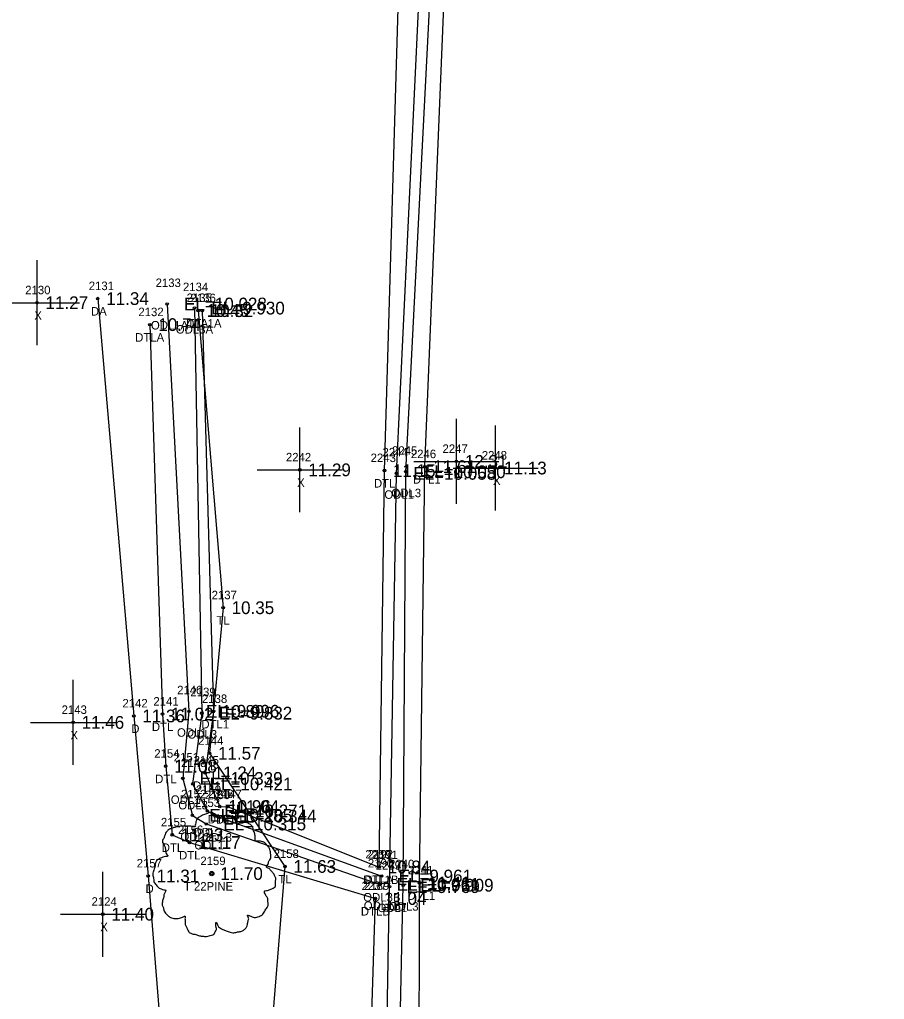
# Model space of a CAD drawing. Extents: x 2042211 to 2045853, y 303080 to 309569.
# Drawn here: x 2044366.6 to 2044468.4, y 304915.7 to 305031.1 of the extents above; entities that cross this region are included whole.
import ezdxf

# ---------------------------------------------------------------- set-up
doc = ezdxf.new("R2010")
doc.units = 0
for name, color, linetype in [('BR_500YR_SCOUR', 7, 'Continuous'), ('RD_EX_Driveway', 7, 'Continuous'), ('RD_EX_Driveway_txCode', 7, 'Continuous'), ('RD_EX_H2O', 7, 'Continuous'), ('RD_EX_H2O_txCode', 7, 'Continuous'), ('RD_EX_Misc', 7, 'Continuous'), ('RD_EX_Misc_txCode', 7, 'Continuous'), ('RD_EX_TX_Driveway_ELEV', 7, 'Continuous'), ('RD_EX_TX_H2O_ELEV', 7, 'Continuous'), ('RD_EX_TX_Misc_ELEV', 7, 'Continuous'), ('RD_EX_TX_VEG_ELEV', 7, 'Continuous'), ('RD_EX_VEG_txCode', 7, 'Continuous'), ('RD_SMD_Locator', 7, 'Continuous')]:
    doc.layers.add(name, color=color, linetype=linetype)

msp = doc.modelspace()

# ---------------------------------------------------------------- linework, layer by layer
at = {"layer": 'BR_500YR_SCOUR'}
msp.add_lwpolyline([(2044387.58, 304996.88), (2044390.53, 304961.86), (2044388.93, 304944.71), (2044397.82, 304931.38), (2044395.87, 304907.56), (2044407.42, 304883.17), (2044412.64, 304877.39), (2044413.34, 304846.91), (2044417.62, 304826.21), (2044417.53, 304827.99), (2044425.41, 304820.87), (2044430.68, 304811.06), (2044486.4, 304757.95), (2044546.53, 304677.07), (2044611.02, 304596.16), (2044662.5, 304521.9), (2044713.91, 304454.08), (2044725.96, 304441.86), (2044733.75, 304433.55)], dxfattribs=at)
for centre, radius in [((2044387.58, 304996.88), 0.15), ((2044390.53, 304961.86), 0.15), ((2044389.38, 304949.64), 0.15), ((2044388.93, 304944.71), 0.15), ((2044397.82, 304931.38), 0.15), ((2044389.19, 304930.54), 0.25), ((2044389.19, 304930.54), 0.15), ((2044389.18, 304930.52), 0.0001)]:
    msp.add_circle(centre, radius, dxfattribs=at)
for points in [[(2044389.32, 304937.71), (2044389.02, 304937.73), (2044388.7, 304937.63), (2044388.45, 304937.53), (2044388.23, 304937.46), (2044388, 304937.36), (2044387.7, 304937.18), (2044387.48, 304936.98), (2044387.35, 304936.73), (2044387.3, 304936.51), (2044387.25, 304936.23), (2044387.25, 304936.06), (2044387.13, 304936.03), (2044386.98, 304936.06), (2044386.73, 304936.13), (2044386.48, 304936.13), (2044386.23, 304936.13), (2044385.88, 304936.11), (2044385.53, 304936.11), (2044385.25, 304936.06), (2044384.93, 304936.01), (2044384.55, 304935.88), (2044384.2, 304935.76), (2044383.9, 304935.51), (2044383.65, 304935.03), (2044383.53, 304934.68), (2044383.38, 304934.44), (2044383.53, 304933.99), (2044383.7, 304933.64), (2044383.73, 304933.44), (2044383.8, 304933.01), (2044383.9, 304932.79), (2044384.03, 304932.59), (2044383.95, 304932.56), (2044383.58, 304932.51), (2044383.28, 304932.41), (2044382.85, 304932.19), (2044382.63, 304931.96), (2044382.53, 304931.64), (2044382.5, 304931.29), (2044382.4, 304931.09), (2044382.33, 304930.81), (2044382.3, 304930.74), (2044382.25, 304930.41), (2044382.35, 304929.96), (2044382.38, 304929.61), (2044382.5, 304929.39), (2044382.65, 304929.21), (2044382.83, 304928.96), (2044383.23, 304928.74), (2044383.55, 304928.64), (2044383.75, 304928.61), (2044383.58, 304928.11), (2044383.53, 304927.76), (2044383.4, 304927.36), (2044383.4, 304927.29), (2044383.35, 304926.81), (2044383.5, 304926.49), (2044383.58, 304926.11), (2044383.75, 304925.89), (2044384.03, 304925.59), (2044384.35, 304925.36), (2044384.85, 304925.24), (2044385.25, 304925.26), (2044385.83, 304925.44), (2044386.08, 304925.51), (2044386.05, 304925.34), (2044386.08, 304924.96), (2044386.08, 304924.54), (2044386.23, 304924.21), (2044386.33, 304923.94), (2044386.48, 304923.69), (2044386.8, 304923.46), (2044387.2, 304923.39), (2044387.63, 304923.24), (2044388.08, 304923.16), (2044388.58, 304923.14), (2044389.17, 304923.29), (2044389.45, 304923.41), (2044389.55, 304923.59), (2044389.75, 304923.96), (2044389.7, 304924.19), (2044389.72, 304924.79), (2044389.82, 304924.61), (2044390, 304924.26), (2044390.5, 304923.96), (2044390.9, 304923.79), (2044391.37, 304923.64), (2044391.67, 304923.56), (2044392.15, 304923.64), (2044392.52, 304923.71), (2044392.9, 304923.84), (2044393.2, 304924.11), (2044393.37, 304924.39), (2044393.42, 304924.66), (2044393.5, 304925.04), (2044393.55, 304925.21)], [(2044393.55, 304925.21), (2044393.47, 304925.39), (2044393.42, 304925.64), (2044393.5, 304925.61), (2044393.67, 304925.56), (2044393.95, 304925.44), (2044394.17, 304925.36), (2044394.5, 304925.39), (2044394.77, 304925.49), (2044395.22, 304925.76), (2044395.5, 304926.24), (2044395.77, 304926.64), (2044395.85, 304926.96), (2044395.8, 304927.19), (2044395.77, 304927.69), (2044395.57, 304927.94), (2044395.52, 304928.06), (2044395.42, 304928.46), (2044395.5, 304928.51), (2044395.77, 304928.56), (2044396.15, 304928.69), (2044396.42, 304928.81), (2044396.65, 304928.99), (2044396.72, 304929.21), (2044396.7, 304929.61), (2044396.75, 304930.01), (2044396.67, 304930.16), (2044396.57, 304930.31), (2044396.5, 304930.51), (2044396.35, 304930.66), (2044396.25, 304930.81), (2044396.15, 304930.91), (2044396.02, 304931.06), (2044395.85, 304931.19), (2044395.7, 304931.24), (2044395.65, 304931.39), (2044395.8, 304931.59), (2044395.85, 304931.69), (2044395.87, 304931.91), (2044396.1, 304932.26), (2044396.15, 304932.66), (2044396.1, 304933.09), (2044396.05, 304933.36), (2044395.9, 304933.64), (2044395.7, 304933.89), (2044395.57, 304934.06), (2044395.4, 304934.19), (2044395.07, 304934.31), (2044394.82, 304934.36), (2044394.47, 304934.36), (2044394.27, 304934.41), (2044394.3, 304934.46), (2044394.3, 304934.61), (2044394.3, 304934.88), (2044394.22, 304935.33), (2044394.07, 304935.83), (2044394.07, 304935.86), (2044393.97, 304936.11), (2044393.75, 304936.31), (2044393.57, 304936.41), (2044393.37, 304936.53), (2044393.12, 304936.56), (2044392.82, 304936.56), (2044392.55, 304936.51), (2044392.35, 304936.41), (2044392.17, 304936.28), (2044392.1, 304936.43), (2044392, 304936.73), (2044391.95, 304936.88), (2044391.8, 304937.06), (2044391.57, 304937.26), (2044391.12, 304937.38), (2044390.5, 304937.31), (2044390.2, 304937.11), (2044390.05, 304936.93), (2044390, 304937.06), (2044389.8, 304937.26), (2044389.7, 304937.43), (2044389.52, 304937.56), (2044389.37, 304937.66), (2044389.27, 304937.71)]]:
    msp.add_spline(points, degree=3, dxfattribs=at)
at = {"layer": 'RD_EX_Driveway'}
msp.add_lwpolyline([(2044375.76, 304998.28), (2044380.01, 304949.11), (2044381.7, 304930.26), (2044386.83, 304866.36)], dxfattribs=at)
at = {"layer": 'RD_EX_H2O'}
for points in [[(2044403.47, 304870.69), (2044407.44, 304869.96), (2044408.86, 304871.35), (2044409.24, 304878.26), (2044410.13, 304929), (2044410.94, 304977.69), (2044415.72, 305077.93), (2044415.23, 305082.87), (2044413.63, 305085.18), (2044400.37, 305083.8), (2044376.8, 305083.33)], [(2044412.68, 304824.61), (2044412.4, 304834.83), (2044410.65, 304865.22), (2044410.04, 304868.77), (2044410.66, 304878.11), (2044411.75, 304929.17), (2044412.06, 304977.88), (2044417.16, 305077.8), (2044420.35, 305084.11), (2044441.54, 305085.32)], [(2044415.25, 304826.5), (2044414.68, 304834.74), (2044412.57, 304868.88), (2044413.59, 304878.38), (2044413.66, 304929.44), (2044414.3, 304978.48), (2044418.39, 305077.45), (2044423.01, 305082.15), (2044441.95, 305081.13)], [(2044408.92, 304931.32), (2044409.54, 304978.02), (2044412.44, 305076.31), (2044400.87, 305076.71), (2044383.06, 305073.87), (2044385, 305069.3)], [(2044383.93, 304997.64), (2044386.51, 304949.66), (2044385.78, 304941.75), (2044386.91, 304937.4), (2044388.55, 304936.38), (2044408.98, 304929.26)], [(2044387.15, 304997.16), (2044388.03, 304949.44), (2044386.94, 304941.1), (2044388.67, 304937.92), (2044389.77, 304937.31), (2044409.21, 304930.25)], [(2044388.07, 304996.86), (2044389.38, 304949.64), (2044388.41, 304942.4), (2044390.13, 304938.44), (2044391.11, 304938.42), (2044408.92, 304931.31)], [(2044381.9, 304995.21), (2044383.39, 304949.33), (2044383.77, 304943.19), (2044384.54, 304935.1), (2044386.58, 304934.2), (2044408.47, 304927.6)], [(2044410.56, 304822.99), (2044408.85, 304834.7), (2044407.58, 304865.58), (2044405.53, 304866.37), (2044405.23, 304866.22), (2044401.8, 304866.57), (2044399.35, 304868.17), (2044399.78, 304872.01), (2044401.54, 304873.59), (2044405.93, 304871.59), (2044407.19, 304871.81), (2044406.92, 304878.34), (2044408.47, 304927.6)]]:
    msp.add_lwpolyline(points, dxfattribs=at)
at = {"layer": 'RD_EX_Misc'}
for p, q in [((2044368.61, 304992.79), (2044368.61, 305002.79)), ((2044363.61, 304997.79), (2044373.61, 304997.79)), ((2044399.56, 304973.1), (2044399.56, 304983.1)), ((2044418.01, 304974.1), (2044418.01, 304984.1)), ((2044422.63, 304973.32), (2044422.63, 304983.32)), ((2044413.01, 304979.1), (2044423.01, 304979.1)), ((2044394.56, 304978.1), (2044404.56, 304978.1)), ((2044417.63, 304978.32), (2044427.63, 304978.32)), ((2044372.86, 304943.35), (2044372.86, 304953.35)), ((2044367.86, 304948.35), (2044377.86, 304948.35)), ((2044376.37, 304920.75), (2044376.37, 304930.75)), ((2044371.37, 304925.75), (2044381.37, 304925.75))]:
    msp.add_line(p, q, dxfattribs=at)
at = {"layer": 'RD_SMD_Locator'}
for centre in [(2044375.76, 304998.28), (2044368.61, 304997.79), (2044383.93, 304997.64), (2044387.15, 304997.16), (2044388.07, 304996.86), (2044381.9, 304995.21), (2044414.3, 304978.48), (2044418.01, 304979.1), (2044422.63, 304978.32), (2044399.56, 304978.1), (2044409.54, 304978.02), (2044410.94, 304977.69), (2044412.06, 304977.88), (2044386.51, 304949.66), (2044388.03, 304949.44), (2044372.86, 304948.35), (2044380.01, 304949.11), (2044383.39, 304949.33), (2044383.77, 304943.19), (2044385.78, 304941.75), (2044388.41, 304942.4), (2044386.94, 304941.1), (2044388.67, 304937.92), (2044390.13, 304938.44), (2044391.11, 304938.42), (2044386.91, 304937.4), (2044389.77, 304937.31), (2044388.55, 304936.38), (2044384.54, 304935.1), (2044386.58, 304934.2), (2044408.92, 304931.32), (2044408.92, 304931.31), (2044381.7, 304930.26), (2044409.21, 304930.25), (2044408.98, 304929.26), (2044410.13, 304929), (2044411.75, 304929.17), (2044413.66, 304929.44), (2044408.47, 304927.6), (2044408.47, 304927.6), (2044376.37, 304925.75)]:
    msp.add_circle(centre, 0.15, dxfattribs=at)

# ---------------------------------------------------------------- texts
at = {"layer": 'RD_EX_Driveway_txCode'}
for s, p in [('2131', (2044374.7, 304999.28)), ('DA', (2044374.96, 304996.28)), ('2142', (2044378.67, 304950.11)), ('D', (2044379.71, 304947.11)), ('2157', (2044380.35, 304931.26)), ('D', (2044381.39, 304928.26))]:
    msp.add_text(s, height=1, dxfattribs=at).set_placement(p)
at = {"layer": 'RD_EX_H2O_txCode'}
for s, p in [('2133', (2044382.58, 304999.64)), ('2134', (2044385.8, 304999.16)), ('2136', (2044386.7, 304997.86)), ('2132', (2044380.55, 304996.21)), ('ODL1A', (2044382.03, 304994.64)), ('DTL1A', (2044386.18, 304994.86)), ('ODL3A', (2044384.96, 304994.16)), ('DTLA', (2044380.17, 304993.21)), ('2244', (2044409.31, 304979.69)), ('2245', (2044410.43, 304979.88)), ('2243', (2044407.91, 304979.02)), ('2246', (2044412.65, 304979.48)), ('DTL1', (2044412.89, 304976.48)), ('DTL', (2044408.3, 304976.02)), ('ODL1', (2044409.53, 304974.69)), ('ODL3', (2044410.36, 304974.88)), ('2140', (2044385.12, 304951.66)), ('2139', (2044386.68, 304951.44)), ('2141', (2044382.32, 304950.33)), ('2138', (2044388.04, 304950.64)), ('DTL', (2044382.14, 304947.33)), ('DTL1', (2044387.97, 304947.64)), ('ODL1', (2044385.1, 304946.66)), ('ODL3', (2044386.33, 304946.44)), ('2154', (2044382.42, 304944.19)), ('2151', (2044384.72, 304943.75)), ('2148', (2044385.59, 304943.1)), ('2145', (2044387.06, 304943.4)), ('DTL', (2044382.52, 304941.19)), ('2152', (2044385.57, 304939.4)), ('DTL1', (2044387, 304940.4)), ('2149', (2044387.32, 304939.92)), ('2150', (2044388.39, 304939.31)), ('2146', (2044388.76, 304939.44)), ('2147', (2044389.76, 304939.42)), ('ODL1', (2044384.37, 304938.75)), ('ODL3', (2044385.25, 304938.1)), ('2153', (2044387.2, 304938.38)), ('2155', (2044383.2, 304936.1)), ('DTL1', (2044388.72, 304936.44)), ('DTL1', (2044389.7, 304936.42)), ('2156', (2044385.21, 304935.2)), ('ODL3', (2044386.97, 304934.92)), ('ODL1', (2044385.5, 304934.4)), ('ODL3', (2044388.08, 304934.31)), ('DTL', (2044383.3, 304933.1)), ('ODL1', (2044387.14, 304933.38)), ('2238', (2044407.29, 304932.32)), ('2192', (2044407.57, 304932.31)), ('DTL', (2044385.34, 304932.2)), ('2190', (2044407.59, 304931.26)), ('2191', (2044408.15, 304932.25)), ('2240', (2044410.08, 304931.17)), ('2239', (2044408.5, 304931)), ('2241', (2044412.32, 304930.44)), ('DTL1B', (2044407.03, 304929.31)), ('DTLA', (2044407.18, 304929.32)), ('2237', (2044406.84, 304928.6)), ('2189', (2044407.13, 304928.6)), ('ODL3B', (2044407.04, 304927.25)), ('DTL1', (2044412.25, 304927.44)), ('DTLB', (2044406.76, 304925.6)), ('DTLB', (2044406.76, 304925.6)), ('ODL1B', (2044407.1, 304926.26)), ('ODL1', (2044408.72, 304926)), ('ODL3', (2044410.06, 304926.17))]:
    msp.add_text(s, height=1, dxfattribs=at).set_placement(p)
at = {"layer": 'RD_EX_Misc_txCode'}
for s, p in [('2130', (2044367.22, 304998.79)), ('X', (2044368.29, 304995.79)), ('2247', (2044416.38, 304980.1)), ('2242', (2044397.93, 304979.1)), ('2248', (2044421, 304979.32)), ('X', (2044417.7, 304977.1)), ('X', (2044422.32, 304976.32)), ('X', (2044399.25, 304976.1)), ('2143', (2044371.51, 304949.35)), ('X', (2044372.55, 304946.35)), ('2124', (2044375.03, 304926.75)), ('X', (2044376.06, 304923.75))]:
    msp.add_text(s, height=1, dxfattribs=at).set_placement(p)
at = {"layer": 'RD_EX_TX_Driveway_ELEV'}
for s, p in [('11.34', (2044376.76, 304997.53)), ('11.36', (2044381.01, 304948.36)), ('11.31', (2044382.7, 304929.51))]:
    msp.add_text(s, height=1.5, dxfattribs=at).set_placement(p)
at = {"layer": 'RD_EX_TX_H2O_ELEV'}
for s, p in [('EL=10.028', (2044385.93, 304996.89)), ('10.32', (2044389.07, 304996.11)), ('EL=9.930', (2044389.15, 304996.41)), ('10.74', (2044382.9, 304994.46)), ('11.15', (2044410.54, 304977.27)), ('EL=10.058', (2044412.94, 304976.94)), ('EL=10.050', (2044414.06, 304977.13)), ('11.61', (2044415.3, 304977.73)), ('11.02', (2044384.39, 304948.58)), ('EL=9.996', (2044388.51, 304948.91)), ('EL=9.832', (2044390.03, 304948.69)), ('10.89', (2044390.38, 304948.89)), ('11.08', (2044384.77, 304942.44)), ('11.24', (2044389.41, 304941.65)), ('EL=10.339', (2044387.78, 304941)), ('EL=10.421', (2044388.94, 304940.35)), ('10.96', (2044391.13, 304937.69)), ('11.04', (2044392.11, 304937.67)), ('EL=10.285', (2044388.91, 304936.65)), ('EL=10.271', (2044390.67, 304937.17)), ('EL=10.344', (2044391.77, 304936.56)), ('EL=10.315', (2044390.55, 304935.63)), ('11.23', (2044385.54, 304934.35)), ('11.17', (2044387.58, 304933.45)), ('10.84', (2044409.92, 304930.56)), ('10.84', (2044409.92, 304930.57)), ('EL=9.961', (2044411.21, 304929.5)), ('EL=10.061', (2044410.98, 304928.51)), ('EL=9.909', (2044413.75, 304928.42)), ('11.41', (2044414.66, 304928.69)), ('EL=9.769', (2044412.13, 304928.25)), ('11.04', (2044409.47, 304926.85)), ('11.04', (2044409.47, 304926.85))]:
    msp.add_text(s, height=1.5, dxfattribs=at).set_placement(p)
at = {"layer": 'RD_EX_TX_Misc_ELEV'}
for s, p in [('11.27', (2044369.61, 304997.04)), ('12.31', (2044419.01, 304978.35)), ('11.29', (2044400.56, 304977.35)), ('11.13', (2044423.63, 304977.57)), ('11.46', (2044373.86, 304947.6)), ('11.40', (2044377.37, 304925))]:
    msp.add_text(s, height=1.5, dxfattribs=at).set_placement(p)
at = {"layer": 'RD_EX_TX_VEG_ELEV'}
for s, p in [('10.45', (2044388.58, 304996.13)), ('10.35', (2044391.53, 304961.11)), ('11.57', (2044389.93, 304943.96)), ('11.70', (2044390.19, 304929.79)), ('11.63', (2044398.82, 304930.63))]:
    msp.add_text(s, height=1.5, dxfattribs=at).set_placement(p)
at = {"layer": 'RD_EX_VEG_txCode'}
for s, p in [('2135', (2044386.23, 304997.88)), ('TLA', (2044386.32, 304994.88)), ('2137', (2044389.18, 304962.86)), ('TL', (2044389.76, 304959.86)), ('2144', (2044387.59, 304945.71)), ('TL', (2044388.16, 304942.71)), ('2158', (2044396.48, 304932.38)), ('2159', (2044387.85, 304931.54)), ('TL', (2044397.05, 304929.38)), ('T 22PINE', (2044385.91, 304928.54))]:
    msp.add_text(s, height=1, dxfattribs=at).set_placement(p)

doc.saveas('drawing.dxf')
